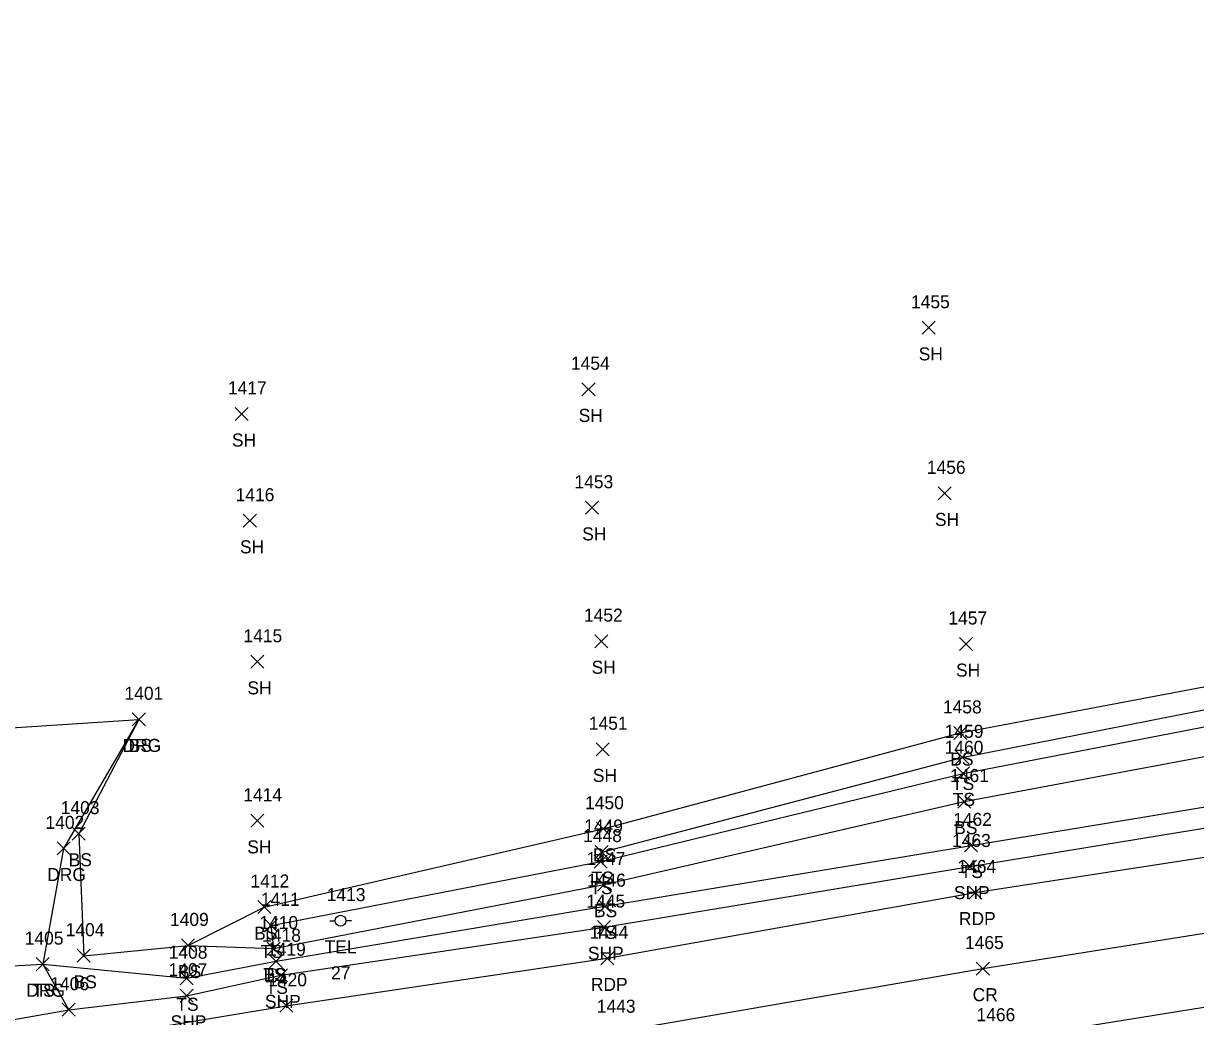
# Model space of a CAD drawing. Extents: x 1497084 to 1499861, y 734741 to 735567.
# Drawn here: x 1498848.7 to 1499028.5, y 735402.7 to 735555 of the extents above; entities that cross this region are included whole.
import ezdxf

# ---------------------------------------------------------------- set-up
doc = ezdxf.new("R2010")
doc.units = 0
for name, color, linetype in [('L_A', 7, 'Continuous'), ('L_I', 7, 'Continuous'), ('L_TIC', 7, 'Continuous'), ('LELB', 7, 'Continuous'), ('P_A', 7, 'Continuous'), ('P_I', 7, 'Continuous'), ('P_TIC', 7, 'Continuous'), ('PET', 7, 'Continuous'), ('PRC', 7, 'Continuous'), ('PSP', 7, 'Continuous'), ('R_A', 7, 'Continuous'), ('R_I', 7, 'Continuous'), ('R_TIC', 7, 'Continuous'), ('RDG', 7, 'Continuous'), ('U_A', 7, 'Continuous'), ('U_C', 7, 'Continuous'), ('U_I', 7, 'Continuous'), ('UP', 7, 'Continuous')]:
    doc.layers.add(name, color=color, linetype=linetype)

msp = doc.modelspace()

# ---------------------------------------------------------------- linework, layer by layer
at = {"layer": 'L_TIC'}
for points in [[(1498986.53, 735507.34), (1498988.53, 735509.34)], [(1498988.53, 735507.34), (1498986.53, 735509.34)], [(1498934.35, 735497.9), (1498936.35, 735499.9)], [(1498936.35, 735497.9), (1498934.35, 735499.9)], [(1498881.16, 735494.12), (1498883.16, 735496.12)], [(1498883.16, 735494.12), (1498881.16, 735496.12)], [(1498989.01, 735481.93), (1498991.01, 735483.93)], [(1498991.01, 735481.93), (1498989.01, 735483.93)], [(1498934.89, 735479.72), (1498936.89, 735481.72)], [(1498936.89, 735479.72), (1498934.89, 735481.72)], [(1498882.39, 735477.73), (1498884.39, 735479.73)], [(1498884.39, 735477.73), (1498882.39, 735479.73)], [(1498936.34, 735459.25), (1498938.34, 735461.25)], [(1498938.34, 735459.25), (1498936.34, 735461.25)], [(1498992.26, 735458.81), (1498994.26, 735460.81)], [(1498994.26, 735458.81), (1498992.26, 735460.81)], [(1498883.54, 735456.09), (1498885.54, 735458.09)], [(1498885.54, 735456.09), (1498883.54, 735458.09)], [(1498865.36, 735447.26), (1498867.36, 735449.26)], [(1498867.36, 735447.26), (1498865.36, 735449.26)], [(1498991.42, 735445.17), (1498993.42, 735447.17)], [(1498993.42, 735445.17), (1498991.42, 735447.17)], [(1498936.52, 735442.66), (1498938.52, 735444.66)], [(1498938.52, 735442.66), (1498936.52, 735444.66)], [(1498991.7, 735441.42), (1498993.7, 735443.42)], [(1498993.7, 735441.42), (1498991.7, 735443.42)], [(1498991.82, 735438.97), (1498993.82, 735440.97)], [(1498993.82, 735438.97), (1498991.82, 735440.97)], [(1498992.01, 735434.64), (1498994.01, 735436.64)], [(1498994.01, 735434.64), (1498992.01, 735436.64)], [(1498883.52, 735431.69), (1498885.52, 735433.69)], [(1498885.52, 735431.69), (1498883.52, 735433.69)], [(1498856.15, 735429.71), (1498858.15, 735431.71)], [(1498858.15, 735429.71), (1498856.15, 735431.71)], [(1498936.6, 735430.47), (1498938.6, 735432.47)], [(1498938.6, 735430.47), (1498936.6, 735432.47)], [(1498993.04, 735427.91), (1498995.04, 735429.91)], [(1498995.04, 735427.91), (1498993.04, 735429.91)], [(1498936.39, 735426.9), (1498938.39, 735428.9)], [(1498938.39, 735426.9), (1498936.39, 735428.9)], [(1498936.22, 735425.43), (1498938.22, 735427.43)], [(1498938.22, 735425.43), (1498936.22, 735427.43)], [(1498936.22, 735425.43), (1498938.22, 735427.43)], [(1498938.22, 735425.43), (1498936.22, 735427.43)], [(1498936.75, 735421.9), (1498938.75, 735423.9)], [(1498938.75, 735421.9), (1498936.75, 735423.9)], [(1498936.88, 735418.58), (1498938.88, 735420.58)], [(1498938.88, 735418.58), (1498936.88, 735420.58)], [(1498884.61, 735418.45), (1498886.61, 735420.45)], [(1498886.61, 735418.45), (1498884.61, 735420.45)], [(1498885.64, 735415.64), (1498887.64, 735417.64)], [(1498887.64, 735415.64), (1498885.64, 735417.64)], [(1498872.92, 735412.56), (1498874.92, 735414.56)], [(1498874.92, 735412.56), (1498872.92, 735414.56)], [(1498872.92, 735412.56), (1498874.92, 735414.56)], [(1498874.92, 735412.56), (1498872.92, 735414.56)], [(1498886.06, 735412.08), (1498888.06, 735414.08)], [(1498888.06, 735412.08), (1498886.06, 735414.08)], [(1498886.06, 735412.08), (1498888.06, 735414.08)], [(1498888.06, 735412.08), (1498886.06, 735414.08)], [(1498850.62, 735409.69), (1498852.62, 735411.69)], [(1498852.62, 735409.69), (1498850.62, 735411.69)], [(1498856.91, 735410.98), (1498858.91, 735412.98)], [(1498858.91, 735410.98), (1498856.91, 735412.98)], [(1498886.41, 735410.13), (1498888.41, 735412.13)], [(1498888.41, 735410.13), (1498886.41, 735412.13)], [(1498872.71, 735407.53), (1498874.71, 735409.53)], [(1498874.71, 735407.53), (1498872.71, 735409.53)]]:
    msp.add_lwpolyline(points, dxfattribs=at)
at = {"layer": 'LELB'}
for points in [[(1498873.92, 735413.56), (1498885.61, 735419.45), (1498937.6, 735431.47), (1498992.42, 735446.17), (1499046.55, 735456.42), (1499100.05, 735466.4), (1499155.3, 735475.02), (1499211.81, 735485.81), (1499272.89, 735498.35), (1499312.63, 735498.22), (1499378.23, 735496.87), (1499423.72, 735498.7), (1499448.77, 735497.16), (1499468.03, 735503.5), (1499479.61, 735506.38), (1499485.8, 735535.79), (1499495.73, 735555.05)], [(1498887.06, 735413.08), (1498886.64, 735416.64), (1498937.22, 735426.43), (1498992.82, 735439.97), (1499047, 735450.43), (1499100.75, 735458.28), (1499155.76, 735466.18), (1499214.75, 735478.18), (1499272.85, 735494.27), (1499312.36, 735493.24), (1499378.42, 735492.78), (1499423.87, 735493.47), (1499447.7, 735493.36), (1499467.98, 735499.39), (1499480.88, 735502.15), (1499491.75, 735532.72), (1499501.47, 735549.91)], [(1498836.02, 735409.82), (1498851.62, 735410.69), (1498873.71, 735408.53), (1498887.41, 735411.13), (1498937.88, 735419.58), (1498994.04, 735428.91), (1499054.48, 735438.88), (1499102.91, 735446.6), (1499157.52, 735455.49), (1499217.09, 735464.03), (1499265.79, 735469.16), (1499273.78, 735473.78), (1499316.12, 735477.44), (1499378.42, 735481.09), (1499425.85, 735484.53), (1499445.24, 735487.28), (1499459.87, 735483.77), (1499494.5, 735481.39), (1499511.88, 735480.66), (1499514.4, 735477.39)], [(1498866.36, 735448.26), (1498857.15, 735430.71), (1498857.91, 735411.98), (1498873.92, 735413.56), (1498887.06, 735413.08), (1498937.75, 735422.9), (1498993.01, 735435.64), (1499049.83, 735446.27), (1499101.27, 735455.9), (1499156.57, 735462.9), (1499215.64, 735473.1), (1499268.79, 735480.58), (1499268.83, 735484.45), (1499283.35, 735488.28), (1499292.38, 735481.13), (1499315.72, 735484.63), (1499378.98, 735487.71)], [(1498937.22, 735426.43), (1498937.39, 735427.9), (1498992.7, 735442.42), (1499047.14, 735453.13), (1499100.52, 735462.11), (1499156.22, 735469.96), (1499214.75, 735478.18)]]:
    msp.add_lwpolyline(points, dxfattribs=at)
at = {"layer": 'P_TIC'}
for points in [[(1498992.87, 735424.67), (1498994.87, 735426.67)], [(1498994.87, 735424.67), (1498992.87, 735426.67)], [(1498993.69, 735420.68), (1498995.69, 735422.68)], [(1498995.69, 735420.68), (1498993.69, 735422.68)], [(1498936.73, 735415.37), (1498938.73, 735417.37)], [(1498938.73, 735415.37), (1498936.73, 735417.37)], [(1498937.22, 735410.59), (1498939.22, 735412.59)], [(1498939.22, 735410.59), (1498937.22, 735412.59)], [(1498887.17, 735407.98), (1498889.17, 735409.98)], [(1498889.17, 735407.98), (1498887.17, 735409.98)], [(1498994.85, 735409.01), (1498996.85, 735411.01)], [(1498996.85, 735409.01), (1498994.85, 735411.01)], [(1498872.7, 735404.84), (1498874.7, 735406.84)], [(1498874.7, 735404.84), (1498872.7, 735406.84)], [(1498854.6, 735402.69), (1498856.6, 735404.69)], [(1498856.6, 735402.69), (1498854.6, 735404.69)], [(1498887.99, 735403.3), (1498889.99, 735405.3)], [(1498889.99, 735403.3), (1498887.99, 735405.3)]]:
    msp.add_lwpolyline(points, dxfattribs=at)
at = {"layer": 'PET'}
for points in [[(1498838.32, 735395.91), (1498888.99, 735404.3), (1498938.22, 735411.59), (1498994.69, 735421.68), (1499054.78, 735430.96), (1499104.38, 735439.6), (1499157.66, 735447.8), (1499219.31, 735457.47), (1499265.92, 735463.89), (1499317.31, 735469.95), (1499378.29, 735473.92), (1499424.75, 735475.7), (1499462.5, 735476.09), (1499495.09, 735475.96), (1499513.91, 735475.18)], [(1498842.44, 735373.21), (1498892.67, 735381.87), (1498940.26, 735389.17), (1498997.67, 735398.94), (1499056.44, 735408.41), (1499108.2, 735417.59), (1499160.18, 735425.34), (1499224.61, 735435.78), (1499269.11, 735441.52), (1499319.5, 735447.91), (1499378.39, 735452.04), (1499424.16, 735454.42), (1499461.26, 735454.74), (1499493.51, 735454.63), (1499512.44, 735453.4), (1499513.2, 735464.25), (1499513.91, 735475.18)]]:
    msp.add_lwpolyline(points, dxfattribs=at)
at = {"layer": 'PRC'}
msp.add_lwpolyline([(1498839.89, 735384.37), (1498890.74, 735392.79), (1498939.31, 735400.24), (1498995.85, 735410.01), (1499056.08, 735419.64), (1499106.34, 735428.63), (1499159.02, 735436.58), (1499221.74, 735447.44), (1499267.15, 735453.23), (1499318.55, 735459.5), (1499378.61, 735463.51), (1499424.29, 735465.34), (1499461.73, 735465.4), (1499494.05, 735465.28), (1499513.2, 735464.25)], dxfattribs=at)
at = {"layer": 'PSP'}
msp.add_lwpolyline([(1498833.8, 735399.85), (1498855.6, 735403.69), (1498873.7, 735405.84), (1498888.17, 735408.98), (1498937.73, 735416.37), (1498993.87, 735425.67), (1499054.79, 735435.66), (1499103.37, 735443.86), (1499157.46, 735452.91), (1499218.03, 735462.22), (1499265.79, 735469.16), (1499316.87, 735474.83), (1499378.34, 735479.55), (1499425.23, 735479.95), (1499462.88, 735477.81), (1499495.09, 735475.96)], dxfattribs=at)
at = {"layer": 'R_TIC'}
for points in [[(1498865.36, 735447.26), (1498867.36, 735449.26)], [(1498867.36, 735447.26), (1498865.36, 735449.26)], [(1498853.82, 735427.45), (1498855.82, 735429.45)], [(1498855.82, 735427.45), (1498853.82, 735429.45)], [(1498850.62, 735409.69), (1498852.62, 735411.69)], [(1498852.62, 735409.69), (1498850.62, 735411.69)], [(1498854.6, 735402.69), (1498856.6, 735404.69)], [(1498856.6, 735402.69), (1498854.6, 735404.69)]]:
    msp.add_lwpolyline(points, dxfattribs=at)
at = {"layer": 'RDG'}
msp.add_lwpolyline([(1498825.62, 735445.59), (1498866.36, 735448.26), (1498854.82, 735428.45), (1498851.62, 735410.69), (1498855.6, 735403.69)], dxfattribs=at)
at = {"layer": 'UP'}
for p, q in [((1498895.65, 735417.36), (1498896.48, 735417.36)), ((1498897.31, 735417.36), (1498897.31, 735417.36)), ((1498898.98, 735417.36), (1498898.15, 735417.36)), ((1498898.15, 735417.36), (1498898.15, 735417.36)), ((1498898.98, 735417.36), (1498898.98, 735417.36))]:
    msp.add_line(p, q, dxfattribs=at)
msp.add_circle((1498897.31, 735417.36), 0.833, dxfattribs=at)

# ---------------------------------------------------------------- texts
at = {"layer": 'L_A'}
for s, p in [('SH', (1498986.01, 735503.34)), ('SH', (1498933.84, 735493.9)), ('SH', (1498880.64, 735490.12)), ('SH', (1498988.5, 735477.93)), ('SH', (1498934.38, 735475.72)), ('SH', (1498881.88, 735473.73)), ('SH', (1498935.83, 735455.25)), ('SH', (1498991.74, 735454.81)), ('SH', (1498883.02, 735452.09)), ('BS', (1498864.8, 735443.26)), ('BS', (1498990.86, 735441.17)), ('SH', (1498936.01, 735438.66)), ('TS', (1498991.11, 735437.42)), ('TS', (1498991.23, 735434.97)), ('BS', (1498991.45, 735430.64)), ('SH', (1498883, 735427.69)), ('BS', (1498855.6, 735425.71)), ('BS', (1498936.05, 735426.47)), ('TS', (1498992.45, 735423.91)), ('TS', (1498935.8, 735422.9)), ('TS', (1498935.63, 735421.43)), ('TS', (1498935.63, 735421.43)), ('BS', (1498936.19, 735417.9)), ('BS', (1498884.05, 735414.45)), ('TS', (1498936.28, 735414.58)), ('TS', (1498885.05, 735411.64)), ('BS', (1498872.36, 735408.56)), ('BS', (1498872.36, 735408.56)), ('TS', (1498885.47, 735408.08)), ('BS', (1498885.5, 735408.08)), ('BS', (1498856.35, 735406.98)), ('TS', (1498885.82, 735406.13)), ('TS', (1498850.03, 735405.69)), ('TS', (1498872.12, 735403.53))]:
    msp.add_text(s, height=2, dxfattribs=at).set_placement(p)
at = {"layer": 'L_I'}
for s, p in [('1455', (1498984.83, 735511.34)), ('1454', (1498932.66, 735501.9)), ('1417', (1498880.03, 735498.12)), ('1456', (1498987.26, 735485.93)), ('1453', (1498933.2, 735483.72)), ('1416', (1498881.21, 735481.73)), ('1452', (1498934.65, 735463.25)), ('1457', (1498990.56, 735462.81)), ('1415', (1498882.41, 735460.09)), ('1401', (1498864.16, 735451.26)), ('1458', (1498989.73, 735449.17)), ('1451', (1498935.4, 735446.66)), ('1459', (1498990, 735445.42)), ('1460', (1498989.99, 735442.97)), ('1461', (1498990.83, 735438.64)), ('1414', (1498882.39, 735435.69)), ('1403', (1498854.38, 735433.71)), ('1450', (1498934.82, 735434.47)), ('1462', (1498991.3, 735431.91)), ('1448', (1498934.53, 735429.43)), ('1448', (1498934.53, 735429.43)), ('1449', (1498934.69, 735430.9)), ('1447', (1498935.05, 735425.9)), ('1412', (1498883.49, 735422.45)), ('1446', (1498935.13, 735422.58)), ('1411', (1498885.08, 735419.64)), ('1404', (1498855.14, 735414.98)), ('1409', (1498871.14, 735416.56)), ('1409', (1498871.14, 735416.56)), ('1410', (1498884.85, 735416.08)), ('1410', (1498884.85, 735416.08)), ('1405', (1498848.85, 735413.69)), ('1418', (1498885.28, 735414.13)), ('1408', (1498870.94, 735411.53))]:
    msp.add_text(s, height=2, dxfattribs=at).set_placement(p)
at = {"layer": 'P_A'}
for s, p in [('SHP', (1498991.41, 735420.67)), ('RDP', (1498992.18, 735416.68)), ('SHP', (1498935.26, 735411.37)), ('RDP', (1498935.71, 735406.59)), ('CR', (1498994.28, 735405.01)), ('SHP', (1498885.7, 735403.98)), ('SHP', (1498871.23, 735400.84))]:
    msp.add_text(s, height=2, dxfattribs=at).set_placement(p)
at = {"layer": 'P_I'}
for s, p in [('1463', (1498991.13, 735428.67)), ('1464', (1498991.95, 735424.68)), ('1445', (1498935.03, 735419.37)), ('1444', (1498935.52, 735414.59)), ('1419', (1498886.03, 735411.98)), ('1465', (1498993.11, 735413.01)), ('1407', (1498870.92, 735408.84)), ('1406', (1498852.77, 735406.69)), ('1420', (1498886.21, 735407.3)), ('1443', (1498936.62, 735403.24)), ('1466', (1498994.88, 735401.94))]:
    msp.add_text(s, height=2, dxfattribs=at).set_placement(p)
at = {"layer": 'R_A'}
for p in [(1498863.85, 735443.26), (1498852.3, 735423.45), (1498849.11, 735405.69)]:
    msp.add_text('DRG', height=2, dxfattribs=at).set_placement(p)
at = {"layer": 'R_I'}
for s, p in [('1401', (1498864.16, 735451.26)), ('1402', (1498852.04, 735431.45)), ('1405', (1498848.85, 735413.69)), ('1406', (1498852.77, 735406.69))]:
    msp.add_text(s, height=2, dxfattribs=at).set_placement(p)
at = {"layer": 'U_A'}
msp.add_text('TEL', height=2, dxfattribs=at).set_placement((1498894.87, 735412.36))
at = {"layer": 'U_C'}
msp.add_text('27', height=2, dxfattribs=at).set_placement((1498895.85, 735408.36))
at = {"layer": 'U_I'}
msp.add_text('1413', height=2, dxfattribs=at).set_placement((1498895.19, 735420.36))

doc.saveas('drawing.dxf')
